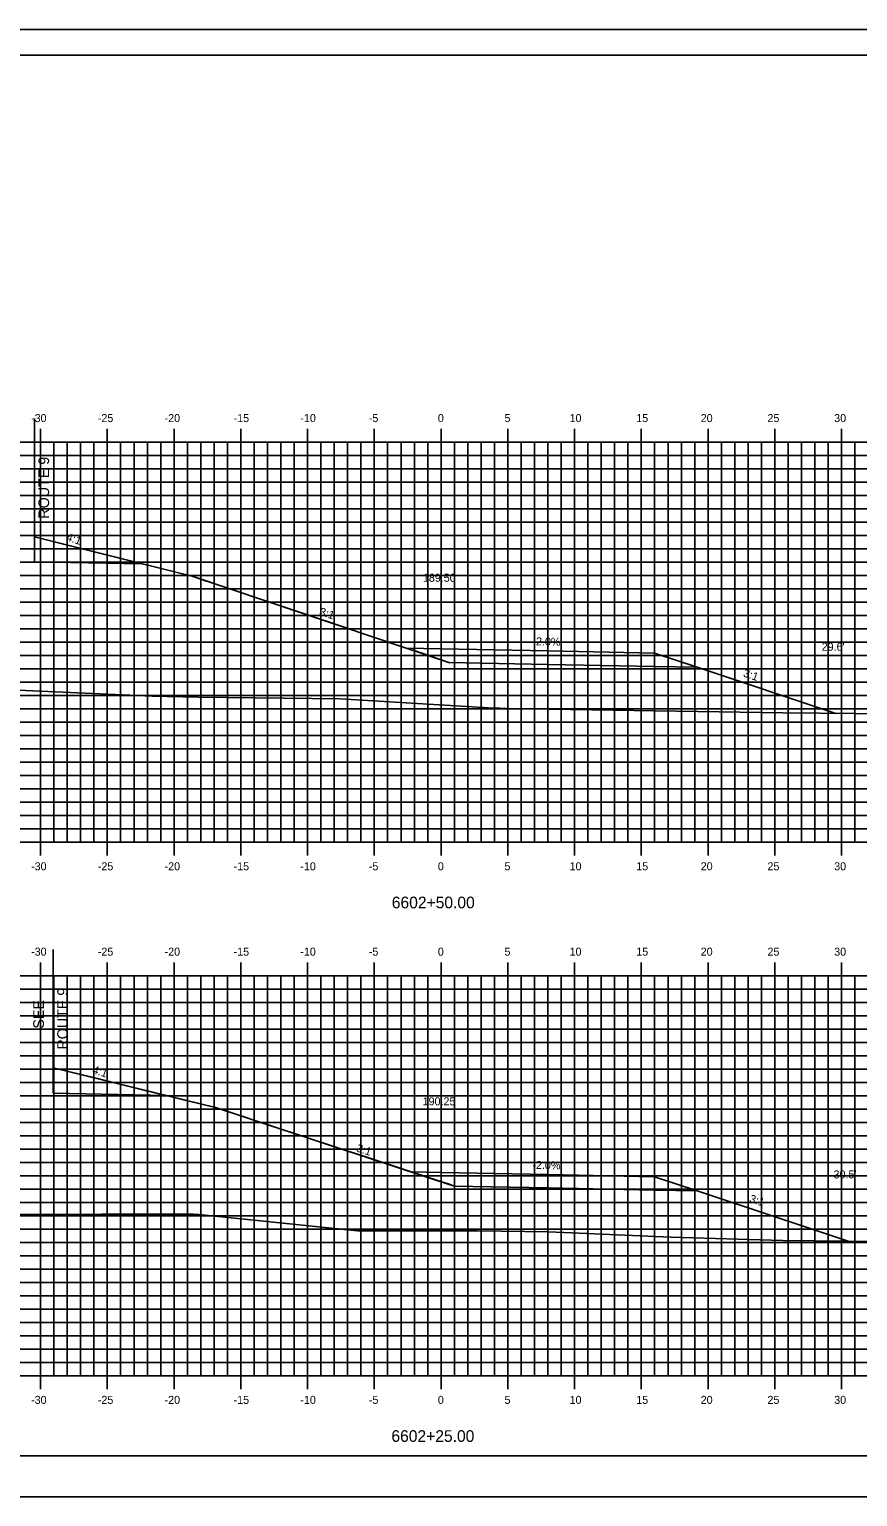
# Model space of a CAD drawing. Extents: x 1724183 to 1724355, y 459560 to 459670.
# Drawn here: x 1724235.4 to 1724297.4, y 459559.6 to 459669.6 of the extents above; entities that cross this region are included whole.
import ezdxf

# ---------------------------------------------------------------- set-up
doc = ezdxf.new("R2010")
doc.units = 0
for name, color, linetype in [('ANNOTATION', 7, 'Continuous'), ('BORDER', 7, 'Continuous'), ('D_Roadway_Centerline', 7, 'Continuous'), ('D_Roadway_Centerline_Text', 7, 'Continuous'), ('D_Roadway_Drive_Gravel', 7, 'Continuous'), ('D_Roadway_Edge_Shoulder', 7, 'Continuous'), ('D_Roadway_SlopeLines', 7, 'Continuous'), ('D_Roadway_SubGrade', 7, 'Continuous'), ('D_Text_Standard', 7, 'Continuous'), ('H_V ANNOTATION', 7, 'Continuous'), ('MAJOR', 7, 'Continuous'), ('MINOR', 7, 'Continuous'), ('PLOT BOUNDARY', 7, 'Continuous'), ('S_Roadway_Centerline', 7, 'Continuous')]:
    doc.layers.add(name, color=color, linetype=linetype)

msp = doc.modelspace()

# ---------------------------------------------------------------- linework, layer by layer
for points in [[(1724266.23, 459623.11), (1724274.23, 459622.95), (1724282.23, 459622.79), (1724285.42, 459621.73), (1724295.81, 459618.27)], [(1724266.23, 459583.86), (1724274.23, 459583.7), (1724282.23, 459583.54), (1724285.42, 459582.48), (1724296.73, 459578.71)]]:
    msp.add_lwpolyline(points)
at = {"layer": 'BORDER'}
msp.add_lwpolyline([(1724191.23, 459562.61), (1724351.23, 459562.61), (1724351.23, 459667.61), (1724191.23, 459667.61)], close=True, dxfattribs=at)
at = {"layer": 'D_Roadway_Centerline'}
for points in [[(1724235.77, 459631.51), (1724238.45, 459630.84), (1724239.65, 459630.54), (1724240.96, 459630.21), (1724243.85, 459629.48), (1724244.87, 459629.23), (1724247.65, 459628.53), (1724248.66, 459628.19), (1724248.76, 459628.16), (1724251.3, 459627.31), (1724252.04, 459627.06), (1724256.37, 459625.61), (1724256.78, 459625.47), (1724257.72, 459625.15), (1724260.43, 459624.24), (1724264.07, 459623.02), (1724264.11, 459623.01), (1724264.15, 459623), (1724266.82, 459622.1)], [(1724237.18, 459591.71), (1724240.4, 459590.92), (1724242.87, 459590.31), (1724244.07, 459590.01), (1724245.65, 459589.63), (1724246.83, 459589.33), (1724249.33, 459588.72), (1724251.77, 459587.92), (1724251.91, 459587.87), (1724253.25, 459587.43), (1724254.33, 459587.08), (1724259.48, 459585.38), (1724259.55, 459585.36), (1724259.68, 459585.32), (1724262.63, 459584.35), (1724266.11, 459583.21), (1724266.76, 459583), (1724267.18, 459582.85), (1724267.22, 459582.84)]]:
    msp.add_lwpolyline(points, dxfattribs=at)
at = {"layer": 'D_Roadway_Drive_Gravel'}
for points in [[(1724266.23, 459623.11), (1724274.23, 459622.95), (1724282.23, 459622.79), (1724285.42, 459621.73), (1724282.23, 459621.79), (1724274.23, 459621.95), (1724266.82, 459622.1)], [(1724266.23, 459583.86), (1724274.23, 459583.7), (1724282.23, 459583.54), (1724285.42, 459582.48), (1724282.23, 459582.54), (1724274.23, 459582.7), (1724267.22, 459582.84)]]:
    msp.add_lwpolyline(points, dxfattribs=at)
at = {"layer": 'D_Roadway_Edge_Shoulder'}
for p, q in [((1724235.77, 459631.51), (1724235.77, 459631.26)), ((1724235.77, 459631.51), (1724235.77, 459631.26)), ((1724237.18, 459591.71), (1724237.18, 459591.46)), ((1724237.18, 459591.71), (1724237.18, 459591.46))]:
    msp.add_line(p, q, dxfattribs=at)
at = {"layer": 'D_Roadway_SlopeLines'}
for points in [[(1724235.77, 459631.51), (1724247.65, 459628.53), (1724266.82, 459622.1)], [(1724235.77, 459631.51), (1724247.65, 459628.53), (1724266.82, 459622.1)], [(1724235.77, 459631.51), (1724247.65, 459628.53), (1724266.82, 459622.1)], [(1724235.77, 459631.51), (1724247.65, 459628.53), (1724266.82, 459622.1)], [(1724235.77, 459631.51), (1724247.65, 459628.53), (1724266.82, 459622.1)], [(1724235.77, 459631.51), (1724247.65, 459628.53), (1724266.82, 459622.1)], [(1724235.77, 459631.51), (1724247.65, 459628.53), (1724266.82, 459622.1)], [(1724282.23, 459622.79), (1724285.42, 459621.73), (1724295.81, 459618.27)], [(1724237.18, 459591.71), (1724249.33, 459588.72), (1724267.22, 459582.84)], [(1724237.18, 459591.71), (1724249.33, 459588.72), (1724267.22, 459582.84)], [(1724237.18, 459591.71), (1724249.33, 459588.72), (1724267.22, 459582.84)], [(1724237.18, 459591.71), (1724249.33, 459588.72), (1724267.22, 459582.84)], [(1724237.18, 459591.71), (1724249.33, 459588.72), (1724267.22, 459582.84)], [(1724237.18, 459591.71), (1724249.33, 459588.72), (1724267.22, 459582.84)], [(1724237.18, 459591.71), (1724249.33, 459588.72), (1724267.22, 459582.84)], [(1724282.23, 459583.54), (1724285.42, 459582.48), (1724296.73, 459578.71)]]:
    msp.add_lwpolyline(points, dxfattribs=at)
at = {"layer": 'D_Roadway_SubGrade'}
for p, q in [((1724235.77, 459640.37), (1724235.77, 459629.64)), ((1724266.23, 459623.11), (1724263.65, 459623.16)), ((1724237.18, 459600.57), (1724237.18, 459589.79)), ((1724266.23, 459583.86), (1724263.98, 459583.91))]:
    msp.add_line(p, q, dxfattribs=at)
for points in [[(1724235.77, 459631.26), (1724235.77, 459631.51), (1724243.85, 459629.48), (1724235.77, 459629.64)], [(1724235.77, 459631.26), (1724235.77, 459631.51), (1724243.85, 459629.48), (1724235.77, 459629.64)], [(1724237.18, 459591.46), (1724237.18, 459591.71), (1724245.65, 459589.63), (1724237.18, 459589.79)], [(1724237.18, 459591.46), (1724237.18, 459591.71), (1724245.65, 459589.63), (1724237.18, 459589.79)]]:
    msp.add_lwpolyline(points, dxfattribs=at)
at = {"layer": 'MAJOR'}
for p, q in [((1724236.23, 459639.61), (1724236.23, 459638.61)), ((1724241.23, 459639.61), (1724241.23, 459638.61)), ((1724246.23, 459639.61), (1724246.23, 459638.61)), ((1724251.23, 459639.61), (1724251.23, 459638.61)), ((1724256.23, 459639.61), (1724256.23, 459638.61)), ((1724261.23, 459639.61), (1724261.23, 459638.61)), ((1724266.23, 459639.61), (1724266.23, 459638.61)), ((1724271.23, 459639.61), (1724271.23, 459638.61)), ((1724276.23, 459639.61), (1724276.23, 459638.61)), ((1724281.23, 459639.61), (1724281.23, 459638.61)), ((1724286.23, 459639.61), (1724286.23, 459638.61)), ((1724291.23, 459639.61), (1724291.23, 459638.61)), ((1724296.23, 459639.61), (1724296.23, 459638.61)), ((1724196.23, 459638.61), (1724336.23, 459638.61)), ((1724196.23, 459638.61), (1724336.23, 459638.61)), ((1724236.23, 459608.61), (1724236.23, 459638.61)), ((1724241.23, 459608.61), (1724241.23, 459638.61)), ((1724246.23, 459608.61), (1724246.23, 459638.61)), ((1724251.23, 459608.61), (1724251.23, 459638.61)), ((1724256.23, 459608.61), (1724256.23, 459638.61)), ((1724261.23, 459608.61), (1724261.23, 459638.61)), ((1724266.23, 459608.61), (1724266.23, 459638.61)), ((1724271.23, 459608.61), (1724271.23, 459638.61)), ((1724276.23, 459608.61), (1724276.23, 459638.61)), ((1724281.23, 459608.61), (1724281.23, 459638.61)), ((1724286.23, 459608.61), (1724286.23, 459638.61)), ((1724291.23, 459608.61), (1724291.23, 459638.61)), ((1724296.23, 459608.61), (1724296.23, 459638.61)), ((1724196.23, 459633.61), (1724336.23, 459633.61)), ((1724196.23, 459628.61), (1724336.23, 459628.61)), ((1724196.23, 459623.61), (1724336.23, 459623.61)), ((1724196.23, 459618.61), (1724336.23, 459618.61)), ((1724196.23, 459613.61), (1724336.23, 459613.61)), ((1724196.23, 459608.61), (1724336.23, 459608.61)), ((1724196.23, 459608.61), (1724336.23, 459608.61)), ((1724236.23, 459607.61), (1724236.23, 459608.61)), ((1724241.23, 459607.61), (1724241.23, 459608.61)), ((1724246.23, 459607.61), (1724246.23, 459608.61)), ((1724251.23, 459607.61), (1724251.23, 459608.61)), ((1724256.23, 459607.61), (1724256.23, 459608.61)), ((1724261.23, 459607.61), (1724261.23, 459608.61)), ((1724266.23, 459607.61), (1724266.23, 459608.61)), ((1724271.23, 459607.61), (1724271.23, 459608.61)), ((1724276.23, 459607.61), (1724276.23, 459608.61)), ((1724281.23, 459607.61), (1724281.23, 459608.61)), ((1724286.23, 459607.61), (1724286.23, 459608.61)), ((1724291.23, 459607.61), (1724291.23, 459608.61)), ((1724296.23, 459607.61), (1724296.23, 459608.61)), ((1724236.23, 459599.61), (1724236.23, 459598.61)), ((1724241.23, 459599.61), (1724241.23, 459598.61)), ((1724246.23, 459599.61), (1724246.23, 459598.61)), ((1724251.23, 459599.61), (1724251.23, 459598.61)), ((1724256.23, 459599.61), (1724256.23, 459598.61)), ((1724261.23, 459599.61), (1724261.23, 459598.61)), ((1724266.23, 459599.61), (1724266.23, 459598.61)), ((1724271.23, 459599.61), (1724271.23, 459598.61)), ((1724276.23, 459599.61), (1724276.23, 459598.61)), ((1724281.23, 459599.61), (1724281.23, 459598.61)), ((1724286.23, 459599.61), (1724286.23, 459598.61)), ((1724291.23, 459599.61), (1724291.23, 459598.61)), ((1724296.23, 459599.61), (1724296.23, 459598.61)), ((1724196.23, 459598.61), (1724336.23, 459598.61)), ((1724196.23, 459598.61), (1724336.23, 459598.61)), ((1724236.23, 459568.61), (1724236.23, 459598.61)), ((1724241.23, 459568.61), (1724241.23, 459598.61)), ((1724246.23, 459568.61), (1724246.23, 459598.61)), ((1724251.23, 459568.61), (1724251.23, 459598.61)), ((1724256.23, 459568.61), (1724256.23, 459598.61)), ((1724261.23, 459568.61), (1724261.23, 459598.61)), ((1724266.23, 459568.61), (1724266.23, 459598.61)), ((1724271.23, 459568.61), (1724271.23, 459598.61)), ((1724276.23, 459568.61), (1724276.23, 459598.61)), ((1724281.23, 459568.61), (1724281.23, 459598.61)), ((1724286.23, 459568.61), (1724286.23, 459598.61)), ((1724291.23, 459568.61), (1724291.23, 459598.61)), ((1724296.23, 459568.61), (1724296.23, 459598.61)), ((1724196.23, 459593.61), (1724336.23, 459593.61)), ((1724196.23, 459588.61), (1724336.23, 459588.61)), ((1724196.23, 459583.61), (1724336.23, 459583.61)), ((1724196.23, 459578.61), (1724336.23, 459578.61)), ((1724196.23, 459573.61), (1724336.23, 459573.61)), ((1724196.23, 459568.61), (1724336.23, 459568.61)), ((1724196.23, 459568.61), (1724336.23, 459568.61)), ((1724236.23, 459567.61), (1724236.23, 459568.61)), ((1724241.23, 459567.61), (1724241.23, 459568.61)), ((1724246.23, 459567.61), (1724246.23, 459568.61)), ((1724251.23, 459567.61), (1724251.23, 459568.61)), ((1724256.23, 459567.61), (1724256.23, 459568.61)), ((1724261.23, 459567.61), (1724261.23, 459568.61)), ((1724266.23, 459567.61), (1724266.23, 459568.61)), ((1724271.23, 459567.61), (1724271.23, 459568.61)), ((1724276.23, 459567.61), (1724276.23, 459568.61)), ((1724281.23, 459567.61), (1724281.23, 459568.61)), ((1724286.23, 459567.61), (1724286.23, 459568.61)), ((1724291.23, 459567.61), (1724291.23, 459568.61)), ((1724296.23, 459567.61), (1724296.23, 459568.61))]:
    msp.add_line(p, q, dxfattribs=at)
at = {"layer": 'MINOR'}
for p, q in [((1724237.23, 459608.61), (1724237.23, 459638.61)), ((1724238.23, 459608.61), (1724238.23, 459638.61)), ((1724239.23, 459608.61), (1724239.23, 459638.61)), ((1724240.23, 459608.61), (1724240.23, 459638.61)), ((1724242.23, 459608.61), (1724242.23, 459638.61)), ((1724243.23, 459608.61), (1724243.23, 459638.61)), ((1724244.23, 459608.61), (1724244.23, 459638.61)), ((1724245.23, 459608.61), (1724245.23, 459638.61)), ((1724247.23, 459608.61), (1724247.23, 459638.61)), ((1724248.23, 459608.61), (1724248.23, 459638.61)), ((1724249.23, 459608.61), (1724249.23, 459638.61)), ((1724250.23, 459608.61), (1724250.23, 459638.61)), ((1724252.23, 459608.61), (1724252.23, 459638.61)), ((1724253.23, 459608.61), (1724253.23, 459638.61)), ((1724254.23, 459608.61), (1724254.23, 459638.61)), ((1724255.23, 459608.61), (1724255.23, 459638.61)), ((1724257.23, 459608.61), (1724257.23, 459638.61)), ((1724258.23, 459608.61), (1724258.23, 459638.61)), ((1724259.23, 459608.61), (1724259.23, 459638.61)), ((1724260.23, 459608.61), (1724260.23, 459638.61)), ((1724262.23, 459608.61), (1724262.23, 459638.61)), ((1724263.23, 459608.61), (1724263.23, 459638.61)), ((1724264.23, 459608.61), (1724264.23, 459638.61)), ((1724265.23, 459608.61), (1724265.23, 459638.61)), ((1724267.23, 459608.61), (1724267.23, 459638.61)), ((1724268.23, 459608.61), (1724268.23, 459638.61)), ((1724269.23, 459608.61), (1724269.23, 459638.61)), ((1724270.23, 459608.61), (1724270.23, 459638.61)), ((1724272.23, 459608.61), (1724272.23, 459638.61)), ((1724273.23, 459608.61), (1724273.23, 459638.61)), ((1724274.23, 459608.61), (1724274.23, 459638.61)), ((1724275.23, 459608.61), (1724275.23, 459638.61)), ((1724277.23, 459608.61), (1724277.23, 459638.61)), ((1724278.23, 459608.61), (1724278.23, 459638.61)), ((1724279.23, 459608.61), (1724279.23, 459638.61)), ((1724280.23, 459608.61), (1724280.23, 459638.61)), ((1724282.23, 459608.61), (1724282.23, 459638.61)), ((1724283.23, 459608.61), (1724283.23, 459638.61)), ((1724284.23, 459608.61), (1724284.23, 459638.61)), ((1724285.23, 459608.61), (1724285.23, 459638.61)), ((1724287.23, 459608.61), (1724287.23, 459638.61)), ((1724288.23, 459608.61), (1724288.23, 459638.61)), ((1724289.23, 459608.61), (1724289.23, 459638.61)), ((1724290.23, 459608.61), (1724290.23, 459638.61)), ((1724292.23, 459608.61), (1724292.23, 459638.61)), ((1724293.23, 459608.61), (1724293.23, 459638.61)), ((1724294.23, 459608.61), (1724294.23, 459638.61)), ((1724295.23, 459608.61), (1724295.23, 459638.61)), ((1724297.23, 459608.61), (1724297.23, 459638.61)), ((1724196.23, 459637.61), (1724336.23, 459637.61)), ((1724196.23, 459636.61), (1724336.23, 459636.61)), ((1724196.23, 459635.61), (1724336.23, 459635.61)), ((1724196.23, 459634.61), (1724336.23, 459634.61)), ((1724196.23, 459632.61), (1724336.23, 459632.61)), ((1724196.23, 459631.61), (1724336.23, 459631.61)), ((1724196.23, 459630.61), (1724336.23, 459630.61)), ((1724196.23, 459629.61), (1724336.23, 459629.61)), ((1724196.23, 459627.61), (1724336.23, 459627.61)), ((1724196.23, 459626.61), (1724336.23, 459626.61)), ((1724196.23, 459625.61), (1724336.23, 459625.61)), ((1724196.23, 459624.61), (1724336.23, 459624.61)), ((1724196.23, 459622.61), (1724336.23, 459622.61)), ((1724196.23, 459621.61), (1724336.23, 459621.61)), ((1724196.23, 459620.61), (1724336.23, 459620.61)), ((1724196.23, 459619.61), (1724336.23, 459619.61)), ((1724196.23, 459617.61), (1724336.23, 459617.61)), ((1724196.23, 459616.61), (1724336.23, 459616.61)), ((1724196.23, 459615.61), (1724336.23, 459615.61)), ((1724196.23, 459614.61), (1724336.23, 459614.61)), ((1724196.23, 459612.61), (1724336.23, 459612.61)), ((1724196.23, 459611.61), (1724336.23, 459611.61)), ((1724196.23, 459610.61), (1724336.23, 459610.61)), ((1724196.23, 459609.61), (1724336.23, 459609.61)), ((1724196.23, 459597.61), (1724336.23, 459597.61)), ((1724237.23, 459568.61), (1724237.23, 459598.61)), ((1724238.23, 459568.61), (1724238.23, 459598.61)), ((1724239.23, 459568.61), (1724239.23, 459598.61)), ((1724240.23, 459568.61), (1724240.23, 459598.61)), ((1724242.23, 459568.61), (1724242.23, 459598.61)), ((1724243.23, 459568.61), (1724243.23, 459598.61)), ((1724244.23, 459568.61), (1724244.23, 459598.61)), ((1724245.23, 459568.61), (1724245.23, 459598.61)), ((1724247.23, 459568.61), (1724247.23, 459598.61)), ((1724248.23, 459568.61), (1724248.23, 459598.61)), ((1724249.23, 459568.61), (1724249.23, 459598.61)), ((1724250.23, 459568.61), (1724250.23, 459598.61)), ((1724252.23, 459568.61), (1724252.23, 459598.61)), ((1724253.23, 459568.61), (1724253.23, 459598.61)), ((1724254.23, 459568.61), (1724254.23, 459598.61)), ((1724255.23, 459568.61), (1724255.23, 459598.61)), ((1724257.23, 459568.61), (1724257.23, 459598.61)), ((1724258.23, 459568.61), (1724258.23, 459598.61)), ((1724259.23, 459568.61), (1724259.23, 459598.61)), ((1724260.23, 459568.61), (1724260.23, 459598.61)), ((1724262.23, 459568.61), (1724262.23, 459598.61)), ((1724263.23, 459568.61), (1724263.23, 459598.61)), ((1724264.23, 459568.61), (1724264.23, 459598.61)), ((1724265.23, 459568.61), (1724265.23, 459598.61)), ((1724267.23, 459568.61), (1724267.23, 459598.61)), ((1724268.23, 459568.61), (1724268.23, 459598.61)), ((1724269.23, 459568.61), (1724269.23, 459598.61)), ((1724270.23, 459568.61), (1724270.23, 459598.61)), ((1724272.23, 459568.61), (1724272.23, 459598.61)), ((1724273.23, 459568.61), (1724273.23, 459598.61)), ((1724274.23, 459568.61), (1724274.23, 459598.61)), ((1724275.23, 459568.61), (1724275.23, 459598.61)), ((1724277.23, 459568.61), (1724277.23, 459598.61)), ((1724278.23, 459568.61), (1724278.23, 459598.61)), ((1724279.23, 459568.61), (1724279.23, 459598.61)), ((1724280.23, 459568.61), (1724280.23, 459598.61)), ((1724282.23, 459568.61), (1724282.23, 459598.61)), ((1724283.23, 459568.61), (1724283.23, 459598.61)), ((1724284.23, 459568.61), (1724284.23, 459598.61)), ((1724285.23, 459568.61), (1724285.23, 459598.61)), ((1724287.23, 459568.61), (1724287.23, 459598.61)), ((1724288.23, 459568.61), (1724288.23, 459598.61)), ((1724289.23, 459568.61), (1724289.23, 459598.61)), ((1724290.23, 459568.61), (1724290.23, 459598.61)), ((1724292.23, 459568.61), (1724292.23, 459598.61)), ((1724293.23, 459568.61), (1724293.23, 459598.61)), ((1724294.23, 459568.61), (1724294.23, 459598.61)), ((1724295.23, 459568.61), (1724295.23, 459598.61)), ((1724297.23, 459568.61), (1724297.23, 459598.61)), ((1724196.23, 459596.61), (1724336.23, 459596.61)), ((1724196.23, 459595.61), (1724336.23, 459595.61)), ((1724196.23, 459594.61), (1724336.23, 459594.61)), ((1724196.23, 459592.61), (1724336.23, 459592.61)), ((1724196.23, 459591.61), (1724336.23, 459591.61)), ((1724196.23, 459590.61), (1724336.23, 459590.61)), ((1724196.23, 459589.61), (1724336.23, 459589.61)), ((1724196.23, 459587.61), (1724336.23, 459587.61)), ((1724196.23, 459586.61), (1724336.23, 459586.61)), ((1724196.23, 459585.61), (1724336.23, 459585.61)), ((1724196.23, 459584.61), (1724336.23, 459584.61)), ((1724196.23, 459582.61), (1724336.23, 459582.61)), ((1724196.23, 459581.61), (1724336.23, 459581.61)), ((1724196.23, 459580.61), (1724336.23, 459580.61)), ((1724196.23, 459579.61), (1724336.23, 459579.61)), ((1724196.23, 459577.61), (1724336.23, 459577.61)), ((1724196.23, 459576.61), (1724336.23, 459576.61)), ((1724196.23, 459575.61), (1724336.23, 459575.61)), ((1724196.23, 459574.61), (1724336.23, 459574.61)), ((1724196.23, 459572.61), (1724336.23, 459572.61)), ((1724196.23, 459571.61), (1724336.23, 459571.61)), ((1724196.23, 459570.61), (1724336.23, 459570.61)), ((1724196.23, 459569.61), (1724336.23, 459569.61))]:
    msp.add_line(p, q, dxfattribs=at)
at = {"layer": 'PLOT BOUNDARY'}
msp.add_lwpolyline([(1724183.14, 459559.55), (1724353.14, 459559.55), (1724353.14, 459669.55), (1724183.14, 459669.55)], close=True, dxfattribs=at)
at = {"layer": 'S_Roadway_Centerline'}
for points in [[(1724196.23, 459621.01), (1724202.87, 459620.97), (1724210.73, 459620.93), (1724221.32, 459620.44), (1724223.87, 459620.3), (1724226.15, 459620.21), (1724235.09, 459620), (1724244.6, 459619.56), (1724248.06, 459619.5), (1724258.68, 459619.37), (1724270.2, 459618.67), (1724270.63, 459618.66), (1724271.14, 459618.64), (1724291.82, 459618.31), (1724294.57, 459618.28), (1724312.67, 459618.11), (1724315.73, 459618.02), (1724319.16, 459618.01), (1724334.32, 459617.92), (1724336.23, 459617.88)], [(1724196.23, 459582.21), (1724199.86, 459582.21), (1724204.03, 459581.98), (1724224.07, 459580.72), (1724224.93, 459580.68), (1724225.67, 459580.68), (1724240.81, 459580.73), (1724247.35, 459580.74), (1724247.69, 459580.74), (1724248.09, 459580.7), (1724259.98, 459579.47), (1724268.97, 459579.48), (1724274.27, 459579.41), (1724283.45, 459579.01), (1724291.81, 459578.76), (1724298.81, 459578.69), (1724312.8, 459578.43), (1724323.48, 459578.03), (1724334.38, 459577.81), (1724336.23, 459577.79)]]:
    msp.add_lwpolyline(points, dxfattribs=at)

# ---------------------------------------------------------------- texts
at = {"layer": 'ANNOTATION'}
for s, height, rotation, p in [('ROUTE 9', 0.8, 90, (1724236.87, 459632.87)), ('4:1', 0.6, 341.5651, (1724238.11, 459631.25)), ('3:1', 0.6, 341.5651, (1724257.07, 459625.66)), ('-2.0%', 0.6, 358.8542, (1724273.07, 459623.38)), ('3:1', 0.6, 341.5651, (1724288.82, 459621.05)), ('ROUTE 9', 0.8, 90, (1724238.28, 459593.07)), ('SEE', 0.8, 90, (1724236.48, 459594.64)), ('4:1', 0.6, 341.5651, (1724240.07, 459591.32)), ('3:1', 0.6, 341.5651, (1724259.84, 459585.45)), ('-2.0%', 0.6, 358.8542, (1724273.07, 459584.13)), ('3:1', 0.6, 341.5651, (1724289.28, 459581.65))]:
    msp.add_text(s, height=height, rotation=rotation, dxfattribs=at).set_placement(p)
at = {"layer": 'D_Roadway_Centerline_Text'}
for s, p in [('189.50', (1724264.87, 459628.14)), ('190.25', (1724264.85, 459588.89))]:
    msp.add_text(s, height=0.6, dxfattribs=at).set_placement(p)
at = {"layer": 'D_Text_Standard'}
for s, p in [("29.6'", (1724294.74, 459622.97)), ("30.5'", (1724295.63, 459583.41))]:
    msp.add_text(s, height=0.6, dxfattribs=at).set_placement(p)
at = {"layer": 'H_V ANNOTATION'}
for s, height, p in [('-30', 0.6, (1724235.52, 459640.11)), ('-25', 0.6, (1724240.52, 459640.11)), ('-20', 0.6, (1724245.52, 459640.11)), ('-15', 0.6, (1724250.69, 459640.11)), ('-10', 0.6, (1724255.69, 459640.11)), ('-5', 0.6, (1724260.82, 459640.11)), ('0', 0.6, (1724265.99, 459640.11)), ('5', 0.6, (1724270.98, 459640.11)), ('10', 0.6, (1724275.86, 459640.11)), ('15', 0.6, (1724280.85, 459640.11)), ('20', 0.6, (1724285.68, 459640.11)), ('25', 0.6, (1724290.68, 459640.11)), ('30', 0.6, (1724295.68, 459640.11)), ('-30', 0.6, (1724235.52, 459606.51)), ('-25', 0.6, (1724240.52, 459606.51)), ('-20', 0.6, (1724245.52, 459606.51)), ('-15', 0.6, (1724250.69, 459606.51)), ('-10', 0.6, (1724255.69, 459606.51)), ('-5', 0.6, (1724260.82, 459606.51)), ('0', 0.6, (1724265.99, 459606.51)), ('5', 0.6, (1724270.98, 459606.51)), ('10', 0.6, (1724275.86, 459606.51)), ('15', 0.6, (1724280.85, 459606.51)), ('20', 0.6, (1724285.68, 459606.51)), ('25', 0.6, (1724290.68, 459606.51)), ('30', 0.6, (1724295.68, 459606.51)), ('6602+50.00', 0.875, (1724262.54, 459603.66)), ('-30', 0.6, (1724235.52, 459600.11)), ('-25', 0.6, (1724240.52, 459600.11)), ('-20', 0.6, (1724245.52, 459600.11)), ('-15', 0.6, (1724250.69, 459600.11)), ('-10', 0.6, (1724255.69, 459600.11)), ('-5', 0.6, (1724260.82, 459600.11)), ('0', 0.6, (1724265.99, 459600.11)), ('5', 0.6, (1724270.98, 459600.11)), ('10', 0.6, (1724275.86, 459600.11)), ('15', 0.6, (1724280.85, 459600.11)), ('20', 0.6, (1724285.68, 459600.11)), ('25', 0.6, (1724290.68, 459600.11)), ('30', 0.6, (1724295.68, 459600.11)), ('-30', 0.6, (1724235.52, 459566.51)), ('-25', 0.6, (1724240.52, 459566.51)), ('-20', 0.6, (1724245.52, 459566.51)), ('-15', 0.6, (1724250.69, 459566.51)), ('-10', 0.6, (1724255.69, 459566.51)), ('-5', 0.6, (1724260.82, 459566.51)), ('0', 0.6, (1724265.99, 459566.51)), ('5', 0.6, (1724270.98, 459566.51)), ('10', 0.6, (1724275.86, 459566.51)), ('15', 0.6, (1724280.85, 459566.51)), ('20', 0.6, (1724285.68, 459566.51)), ('25', 0.6, (1724290.68, 459566.51)), ('30', 0.6, (1724295.68, 459566.51)), ('6602+25.00', 0.875, (1724262.51, 459563.66))]:
    msp.add_text(s, height=height, dxfattribs=at).set_placement(p)

doc.saveas('drawing.dxf')
